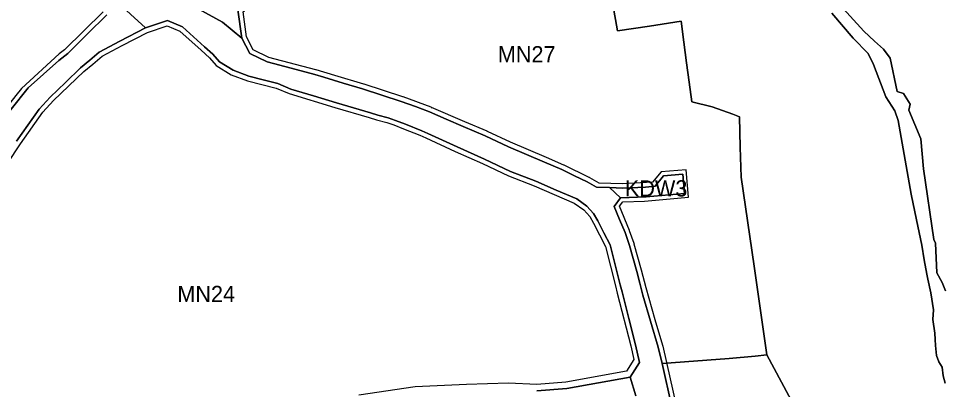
# Model space of a CAD drawing. Extents: x 7440055 to 7442242, y 5549003 to 5552256.
# Drawn here: x 7440932 to 7441503, y 5550451 to 5550680 of the extents above; entities that cross this region are included whole.
import ezdxf

# ---------------------------------------------------------------- set-up
doc = ezdxf.new("R2010")
doc.units = 0
for name, color, linetype in [('linie_rozgraniczajace', 7, 'Continuous'), ('linie_zabudowy_nieprzekraczalne', 7, 'Continuous'), ('oznaczenia_przeznaczen', 7, 'Continuous')]:
    doc.layers.add(name, color=color, linetype=linetype)

msp = doc.modelspace()

# ---------------------------------------------------------------- linework, layer by layer
at = {"layer": 'linie_rozgraniczajace'}
for points in [[(7441435.31, 5550693.52), (7441454.24, 5550672.51), (7441460.78, 5550666.21), (7441466.44, 5550661.26), (7441470.53, 5550655.67), (7441474.81, 5550635.24), (7441478.78, 5550633.85), (7441482.88, 5550627.29), (7441482.11, 5550623.73), (7441489.5, 5550606), (7441491.16, 5550587.28), (7441497.49, 5550543.64), (7441498.59, 5550541.39), (7441499.26, 5550523.22), (7441502.65, 5550517.13), (7441504.74, 5550512.02)], [(7441504.74, 5550512.02), (7441502.65, 5550517.13), (7441499.26, 5550523.22), (7441498.59, 5550541.39), (7441497.49, 5550543.64), (7441491.16, 5550587.28), (7441489.5, 5550606), (7441482.11, 5550623.73), (7441482.88, 5550627.29), (7441478.78, 5550633.85), (7441474.81, 5550635.24), (7441470.53, 5550655.67), (7441466.44, 5550661.26), (7441460.78, 5550666.21), (7441454.24, 5550672.51), (7441435.31, 5550693.52)], [(7440991.64, 5550691.44), (7441010.3, 5550674.43), (7440994.4, 5550666.25), (7440981.7, 5550659.44), (7440975.74, 5550654.43), (7440970.13, 5550649.74), (7440960.72, 5550640.75), (7440951.3, 5550631.76), (7440944.53, 5550624.33), (7440937.54, 5550614.43), (7440930.55, 5550604.54)], [(7441313.22, 5550447.05), (7441309.89, 5550458.66), (7441315.58, 5550467.66), (7441313.05, 5550478.63), (7441308.9, 5550494.99), (7441304.76, 5550511.34), (7441303.64, 5550515.76), (7441300.52, 5550528.12), (7441297.39, 5550540.46), (7441293.61, 5550547.88), (7441289.83, 5550555.3), (7441287.21, 5550559.69), (7441283.1, 5550564.36), (7441276.76, 5550568.87), (7441264.15, 5550574.27), (7441251.54, 5550579.67), (7441235.79, 5550585.77), (7441219.75, 5550593.39), (7441202.79, 5550600.89), (7441184.75, 5550609.2), (7441181.08, 5550610.92), (7441170.86, 5550614.93), (7441164.83, 5550617.32), (7441160.18, 5550618.85), (7441153.89, 5550620.61), (7441149.3, 5550621.95), (7441138.75, 5550625.02), (7441128.2, 5550628.1), (7441114.15, 5550632.39), (7441100.11, 5550636.68), (7441092, 5550640.13), (7441083.05, 5550642.34), (7441074.1, 5550644.55), (7441064.51, 5550648.26), (7441055.91, 5550653.51), (7441051.89, 5550658.18), (7441046.67, 5550662.85), (7441033.06, 5550675.08), (7441023.83, 5550678.97), (7441010.3, 5550674.43), (7440991.64, 5550691.44)], [(7441299.05, 5550688.91), (7441302.05, 5550672.64), (7441321.71, 5550675.62), (7441341.37, 5550678.59), (7441342.96, 5550665.75), (7441344.55, 5550652.91), (7441346.23, 5550640.84), (7441347.91, 5550628.77), (7441360.57, 5550625.76), (7441373.17, 5550621.09), (7441377.36, 5550619.54), (7441377.86, 5550600.83), (7441378.36, 5550582.13), (7441386.33, 5550527.25), (7441394.29, 5550472.38), (7441387.13, 5550471.73), (7441370.93, 5550470.27), (7441329.53, 5550467.05), (7441329.52, 5550467.11), (7441327.15, 5550477.22), (7441317.64, 5550509.31), (7441315.73, 5550516.67), (7441313.81, 5550524.03), (7441309.44, 5550540.09), (7441306.61, 5550548.11), (7441303.28, 5550556.15), (7441299.94, 5550564.19), (7441303.82, 5550569.43), (7441319.7, 5550570.12), (7441343.35, 5550572.16), (7441342.31, 5550584.12), (7441330.36, 5550583.09), (7441325.19, 5550576.62), (7441319.32, 5550576.11), (7441305.32, 5550575.53), (7441297.11, 5550575.76), (7441288.9, 5550575.99), (7441283.26, 5550579.36), (7441275.44, 5550583.15), (7441267.62, 5550586.94), (7441262.24, 5550589.25), (7441256.86, 5550591.55), (7441234.66, 5550601.07), (7441220.27, 5550607.79), (7441206.5, 5550613.59), (7441196.14, 5550618.1), (7441185.79, 5550622.6), (7441177.05, 5550625.8), (7441168.32, 5550629.01), (7441156.37, 5550632.88), (7441144.41, 5550636.76), (7441132.39, 5550640.38), (7441120.37, 5550644), (7441114.9, 5550645.62), (7441100.21, 5550649.51), (7441085.51, 5550653.4), (7441074.7, 5550658.69), (7441069.74, 5550668.05), (7441067.3, 5550685.62)], [(7441416.82, 5550430.21), (7441394.29, 5550472.38), (7441386.33, 5550527.25), (7441378.36, 5550582.13), (7441377.86, 5550600.83), (7441377.36, 5550619.54), (7441373.17, 5550621.09), (7441360.57, 5550625.76), (7441347.91, 5550628.77), (7441346.23, 5550640.84), (7441344.55, 5550652.91), (7441342.96, 5550665.75), (7441341.37, 5550678.59), (7441321.71, 5550675.62), (7441302.05, 5550672.64), (7441299.05, 5550688.91)], [(7440986.37, 5550682.63), (7440974.26, 5550670.64), (7440962.15, 5550658.65), (7440956.69, 5550654.35), (7440937.69, 5550637.36), (7440927.23, 5550624.19), (7440906.38, 5550597.1), (7440895.14, 5550582.1), (7440886.56, 5550571.01), (7440877.43, 5550570.75), (7440862.74, 5550580.86)], [(7440927.23, 5550624.19), (7440937.69, 5550637.36), (7440956.69, 5550654.35), (7440962.15, 5550658.65), (7440974.26, 5550670.64), (7440986.37, 5550682.63)], [(7441043.14, 5550686.11), (7441057.84, 5550678.1), (7441069.74, 5550668.05), (7441074.7, 5550658.69), (7441085.51, 5550653.4), (7441100.21, 5550649.51), (7441114.9, 5550645.62), (7441120.37, 5550644), (7441132.39, 5550640.38), (7441144.41, 5550636.76), (7441156.37, 5550632.88), (7441168.32, 5550629.01), (7441177.05, 5550625.8), (7441185.79, 5550622.6), (7441196.14, 5550618.1), (7441206.5, 5550613.59), (7441220.27, 5550607.79), (7441234.66, 5550601.07), (7441256.86, 5550591.55), (7441262.24, 5550589.25), (7441267.62, 5550586.94), (7441275.44, 5550583.15), (7441283.26, 5550579.36), (7441288.9, 5550575.99), (7441297.11, 5550575.76), (7441303.82, 5550569.43), (7441299.94, 5550564.19), (7441303.28, 5550556.15), (7441306.61, 5550548.11), (7441309.44, 5550540.09), (7441313.81, 5550524.03), (7441315.73, 5550516.67), (7441317.64, 5550509.31), (7441327.15, 5550477.22), (7441329.52, 5550467.11), (7441329.53, 5550467.05), (7441335.5, 5550440.32)], [(7441067.3, 5550685.62), (7441069.74, 5550668.05), (7441057.84, 5550678.1), (7441043.14, 5550686.11)], [(7441504.45, 5550455.02), (7441503.17, 5550459.51), (7441502.58, 5550464.83), (7441500.56, 5550468.22), (7441499.15, 5550472.1), (7441498.56, 5550478.15), (7441498.34, 5550481.95), (7441498.12, 5550485.76), (7441496.86, 5550494.25), (7441497.29, 5550500.29), (7441495.64, 5550510.78), (7441493.79, 5550519.11), (7441493.21, 5550522.32), (7441491.59, 5550531.22), (7441489.97, 5550540.12), (7441486.67, 5550555.93), (7441483.38, 5550571.74), (7441475.5, 5550617.3), (7441473.32, 5550623.27), (7441467.8, 5550631.79), (7441460.28, 5550651.83), (7441456.86, 5550658.73), (7441447.56, 5550668.14), (7441434.5, 5550683.51)], [(7441434.5, 5550683.51), (7441447.56, 5550668.14), (7441456.86, 5550658.73), (7441460.28, 5550651.83), (7441467.8, 5550631.79), (7441473.32, 5550623.27), (7441475.5, 5550617.3), (7441483.38, 5550571.74), (7441486.67, 5550555.93), (7441489.97, 5550540.12), (7441491.59, 5550531.22), (7441493.21, 5550522.32), (7441493.79, 5550519.11), (7441495.64, 5550510.78), (7441497.29, 5550500.29), (7441496.86, 5550494.25), (7441498.12, 5550485.76), (7441498.34, 5550481.95), (7441498.56, 5550478.15), (7441499.15, 5550472.1), (7441500.56, 5550468.22), (7441502.58, 5550464.83), (7441503.17, 5550459.51), (7441504.45, 5550455.02)], [(7440930.55, 5550604.54), (7440937.54, 5550614.43), (7440944.53, 5550624.33), (7440951.3, 5550631.76), (7440960.72, 5550640.75), (7440970.13, 5550649.74), (7440975.74, 5550654.43), (7440981.7, 5550659.44), (7440994.4, 5550666.25), (7441010.3, 5550674.43), (7441023.83, 5550678.97), (7441033.06, 5550675.08), (7441046.67, 5550662.85), (7441051.89, 5550658.18), (7441055.91, 5550653.51), (7441064.51, 5550648.26), (7441074.1, 5550644.55), (7441083.05, 5550642.34), (7441092, 5550640.13), (7441100.11, 5550636.68), (7441114.15, 5550632.39), (7441128.2, 5550628.1), (7441138.75, 5550625.02), (7441149.3, 5550621.95), (7441153.89, 5550620.61), (7441160.18, 5550618.85), (7441164.83, 5550617.32), (7441170.86, 5550614.93), (7441181.08, 5550610.92), (7441184.75, 5550609.2), (7441202.79, 5550600.89), (7441219.75, 5550593.39), (7441235.79, 5550585.77), (7441251.54, 5550579.67), (7441264.15, 5550574.27), (7441276.76, 5550568.87), (7441283.1, 5550564.36), (7441287.21, 5550559.69), (7441289.83, 5550555.3), (7441293.61, 5550547.88), (7441297.39, 5550540.46), (7441300.52, 5550528.12), (7441303.64, 5550515.76), (7441304.76, 5550511.34), (7441308.9, 5550494.99), (7441313.05, 5550478.63), (7441315.58, 5550467.66), (7441309.89, 5550458.66), (7441270.6, 5550451.55), (7441252.14, 5550450.16)], [(7441335.5, 5550440.32), (7441329.53, 5550467.05), (7441370.93, 5550470.27), (7441387.13, 5550471.73), (7441394.29, 5550472.38), (7441416.82, 5550430.21)], [(7441252.14, 5550450.16), (7441270.6, 5550451.55), (7441309.89, 5550458.66), (7441313.22, 5550447.05)]]:
    msp.add_lwpolyline(points, dxfattribs=at)
msp.add_lwpolyline([(7441297.11, 5550575.76), (7441305.32, 5550575.53), (7441319.32, 5550576.11), (7441325.19, 5550576.62), (7441330.36, 5550583.09), (7441342.31, 5550584.12), (7441343.35, 5550572.16), (7441319.7, 5550570.12), (7441303.82, 5550569.43)], close=True, dxfattribs=at)
at = {"layer": 'linie_zabudowy_nieprzekraczalne'}
for p, q in [((7441268.99, 5550589.61), (7441268.73, 5550589.73)), ((7441316.72, 5550524.77), (7441316.7, 5550524.83))]:
    msp.add_line(p, q, dxfattribs=at)
for points in [[(7440983.99, 5550684.49), (7440960.16, 5550660.9), (7440956.96, 5550658.38), (7440933.66, 5550637.11), (7440930.11, 5550632.64), (7440915.87, 5550614.78), (7440898.36, 5550591.41), (7440885.83, 5550574.99), (7440878.62, 5550574.79), (7440865.22, 5550584.01), (7440855.23, 5550592.9), (7440850.69, 5550595.14), (7440832.28, 5550607), (7440820.91, 5550612.13), (7440771.27, 5550615.49), (7440751.11, 5550613.68)], [(7441115.62, 5550648.54), (7441086.56, 5550656.22), (7441076.89, 5550660.96), (7441072.64, 5550668.99), (7441070.51, 5550684.29), (7441071.53, 5550685.05)], [(7440924.9, 5550590.77), (7440933.02, 5550602.83), (7440946.87, 5550622.45), (7440953.45, 5550629.66), (7440972.13, 5550647.5), (7440977.67, 5550652.13), (7440983.4, 5550656.95), (7440995.79, 5550663.59), (7441011.47, 5550671.66), (7441023.71, 5550675.76), (7441031.43, 5550672.51), (7441044.67, 5550660.62), (7441049.74, 5550656.07), (7441053.95, 5550651.19), (7441063.18, 5550645.56), (7441073.19, 5550641.68), (7441091.05, 5550637.28), (7441099.08, 5550633.85), (7441127.35, 5550625.22), (7441148.46, 5550619.07), (7441153.06, 5550617.72), (7441159.31, 5550615.98), (7441163.81, 5550614.49), (7441169.76, 5550612.14), (7441179.89, 5550608.16), (7441183.49, 5550606.48), (7441201.56, 5550598.16), (7441218.5, 5550590.66), (7441234.6, 5550583.01), (7441250.41, 5550576.9), (7441275.28, 5550566.24), (7441281.08, 5550562.12), (7441284.77, 5550557.91), (7441287.21, 5550553.85), (7441294.57, 5550539.4), (7441300.73, 5550515.03), (7441301.85, 5550510.61), (7441310.14, 5550477.93), (7441312.06, 5550469.58), (7441307.45, 5550462.28), (7441270.09, 5550455.52), (7441252.08, 5550454.16), (7441234.66, 5550454.88), (7441208.68, 5550454.14), (7441177.01, 5550452.71), (7441142.08, 5550447.51)], [(7441127.24, 5550645.07), (7441115.81, 5550648.48)], [(7441145.25, 5550639.64), (7441127.25, 5550645.07)], [(7441169.19, 5550631.88), (7441145.37, 5550639.61)], [(7441186.74, 5550625.45), (7441169.4, 5550631.8)], [(7441221.38, 5550610.57), (7441207.68, 5550616.35), (7441187.07, 5550625.32)], [(7441268.73, 5550589.73), (7441258.04, 5550594.31), (7441235.88, 5550603.8), (7441221.59, 5550610.48)], [(7441284.45, 5550582.12), (7441268.99, 5550589.61)], [(7441309.35, 5550549.34), (7441303.17, 5550564.24), (7441305.32, 5550566.97), (7441318.59, 5550567.47), (7441345.93, 5550569.89), (7441344.43, 5550586.8), (7441329, 5550585.43), (7441323.63, 5550579.09), (7441305.07, 5550578.13), (7441290.63, 5550578.45), (7441284.92, 5550581.87)], [(7441312.23, 5550541.19), (7441309.46, 5550549.03)], [(7441316.7, 5550524.83), (7441312.36, 5550540.77)], [(7441330, 5550478.16), (7441325.27, 5550494.11), (7441319.58, 5550513.79), (7441316.72, 5550524.77)], [(7441332.44, 5550467.81), (7441330.09, 5550477.83)], [(7441383.29, 5550355.97), (7441369.09, 5550370.21), (7441355.41, 5550389.9), (7441343.22, 5550424.11), (7441338.41, 5550441.05), (7441332.45, 5550467.75)]]:
    msp.add_lwpolyline(points, dxfattribs=at)
for centre, radius, start, end in [((7441114.73, 5550645.38), 3.29, 70.7387, 74.2101), ((7441127.25, 5550645.07), 0.00707, 315, 135), ((7441145.21, 5550639.25), 0.397, 66.9911, 84.9364), ((7441168.04, 5550628.53), 3.54, 67.3272, 70.9638), ((7441187.79, 5550627.64), 2.43, 244.3092, 252.6879), ((7441220.51, 5550608.25), 2.48, 64.1589, 69.444), ((7441282.23, 5550577.37), 5.24, 59.08, 64.9017), ((7441307.41, 5550548.48), 2.12, 15.0893, 23.984), ((7441308.79, 5550539.87), 3.69, 14.2478, 20.9371), ((7441326.03, 5550476.9), 4.17, 12.9018, 17.6084), ((7441332.54, 5550467.79), 0.0962, 171.0274, 207.8973)]:
    msp.add_arc(centre, radius, start, end, dxfattribs=at)

# ---------------------------------------------------------------- texts
at = {"layer": 'oznaczenia_przeznaczen'}
for s, p in [('MN27', (7441228, 5550653.2)), ('KDW3', (7441306.52, 5550570.31)), ('MN24', (7441029.92, 5550505.08))]:
    msp.add_text(s, height=10, dxfattribs=at).set_placement(p)

doc.saveas('drawing.dxf')
